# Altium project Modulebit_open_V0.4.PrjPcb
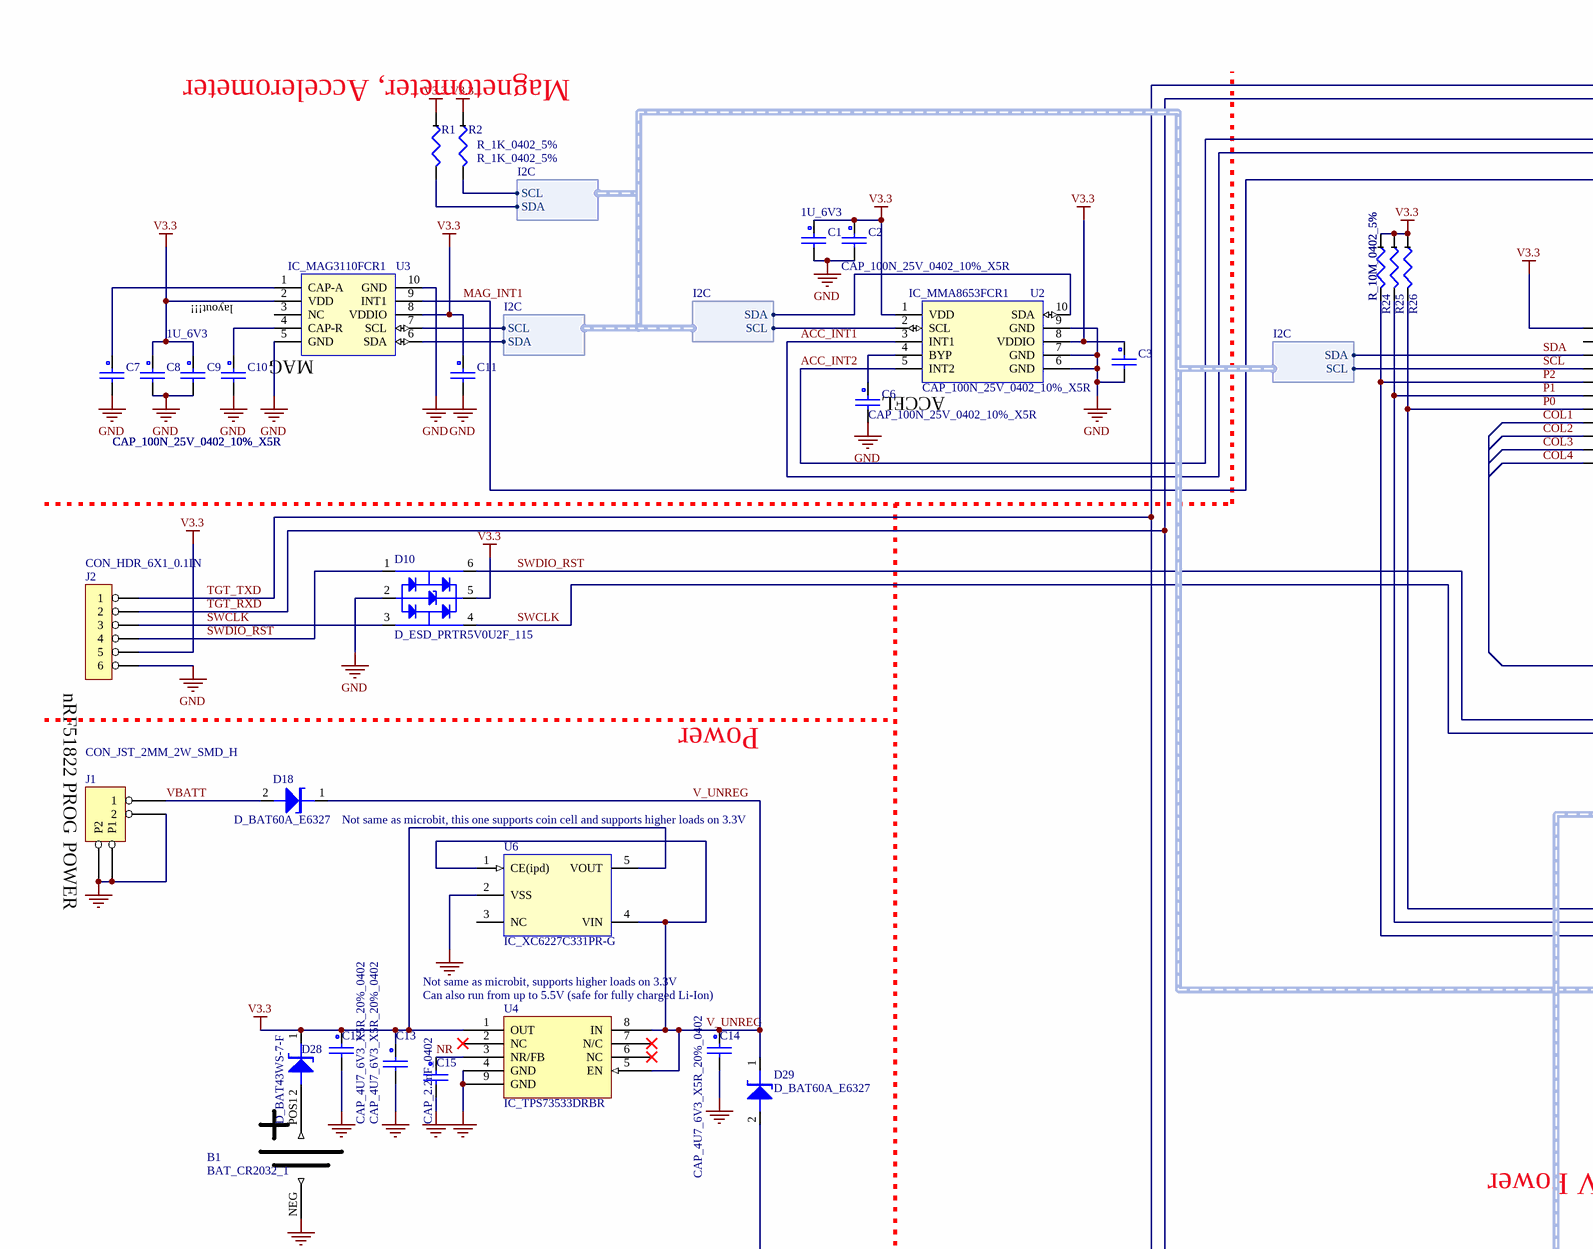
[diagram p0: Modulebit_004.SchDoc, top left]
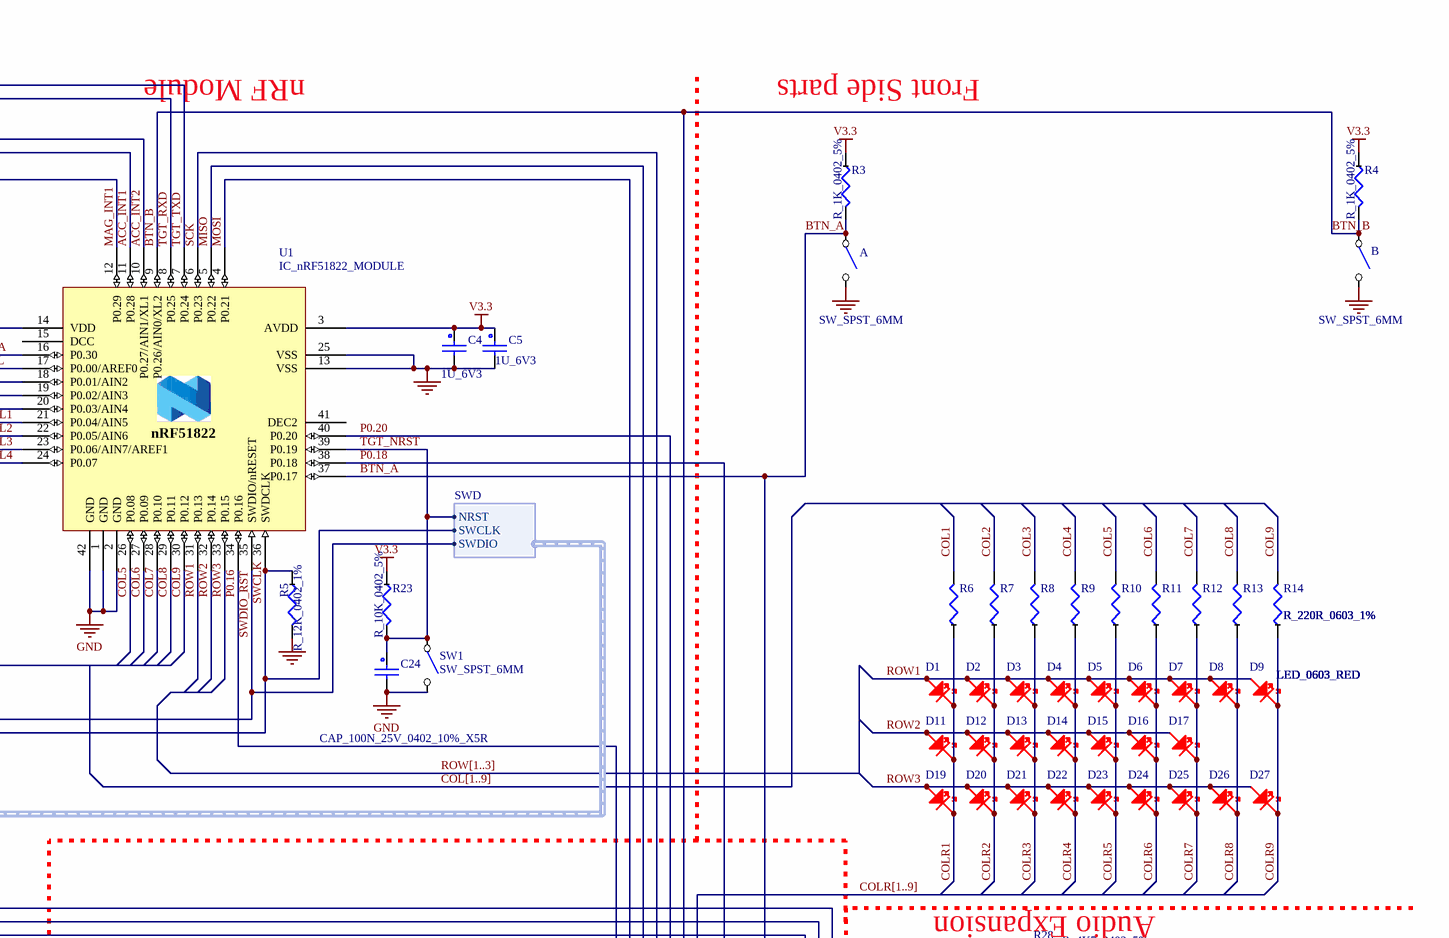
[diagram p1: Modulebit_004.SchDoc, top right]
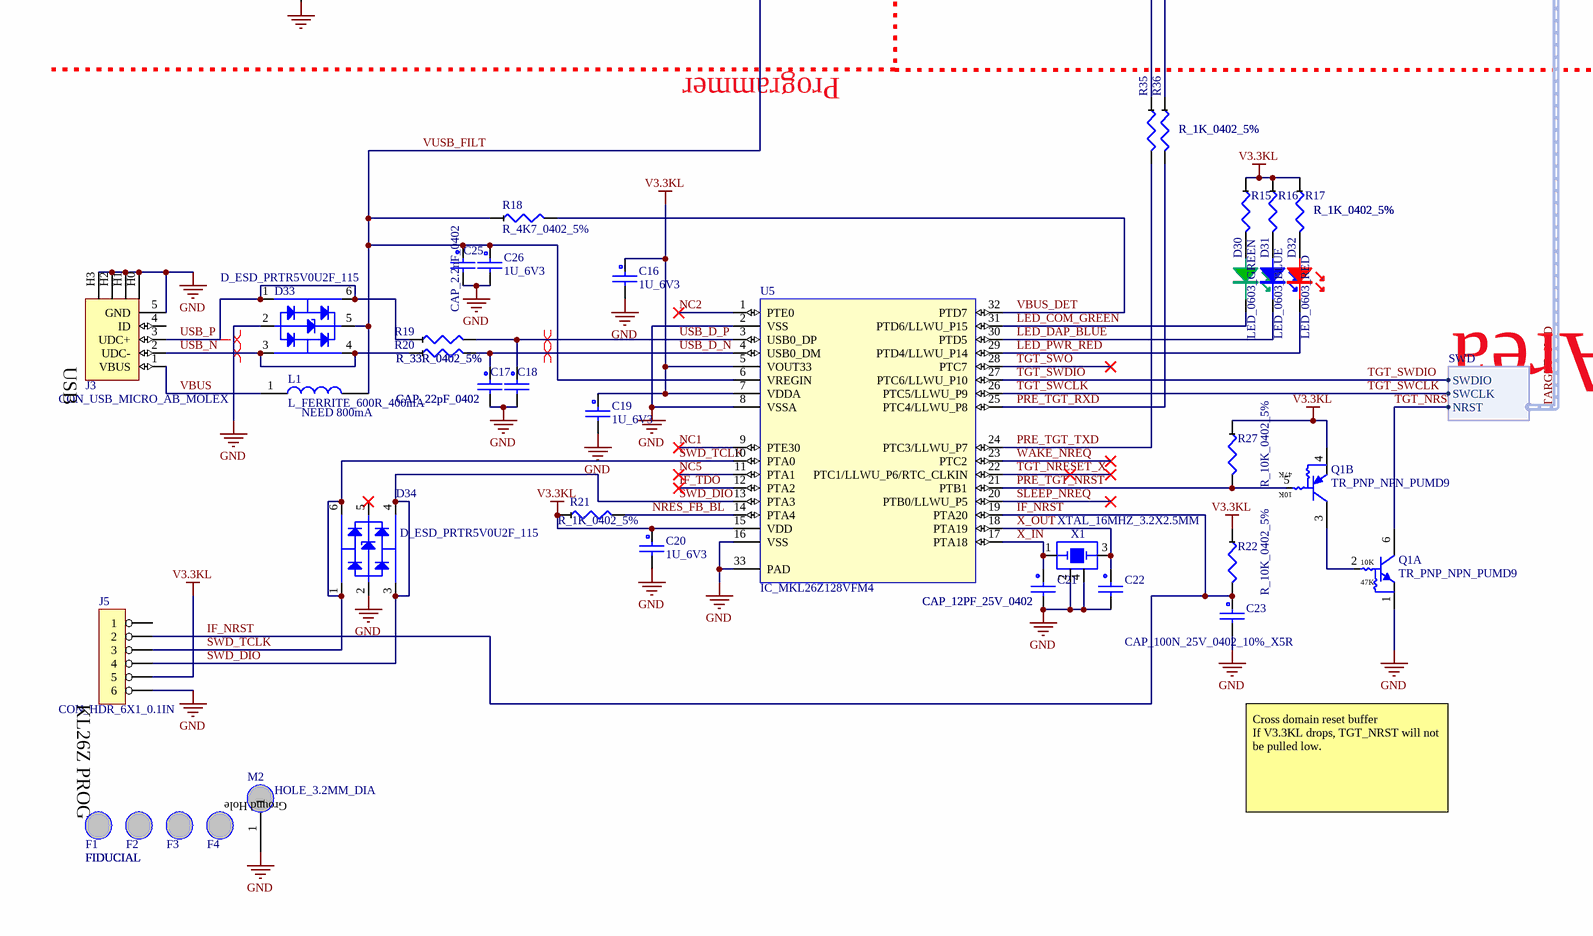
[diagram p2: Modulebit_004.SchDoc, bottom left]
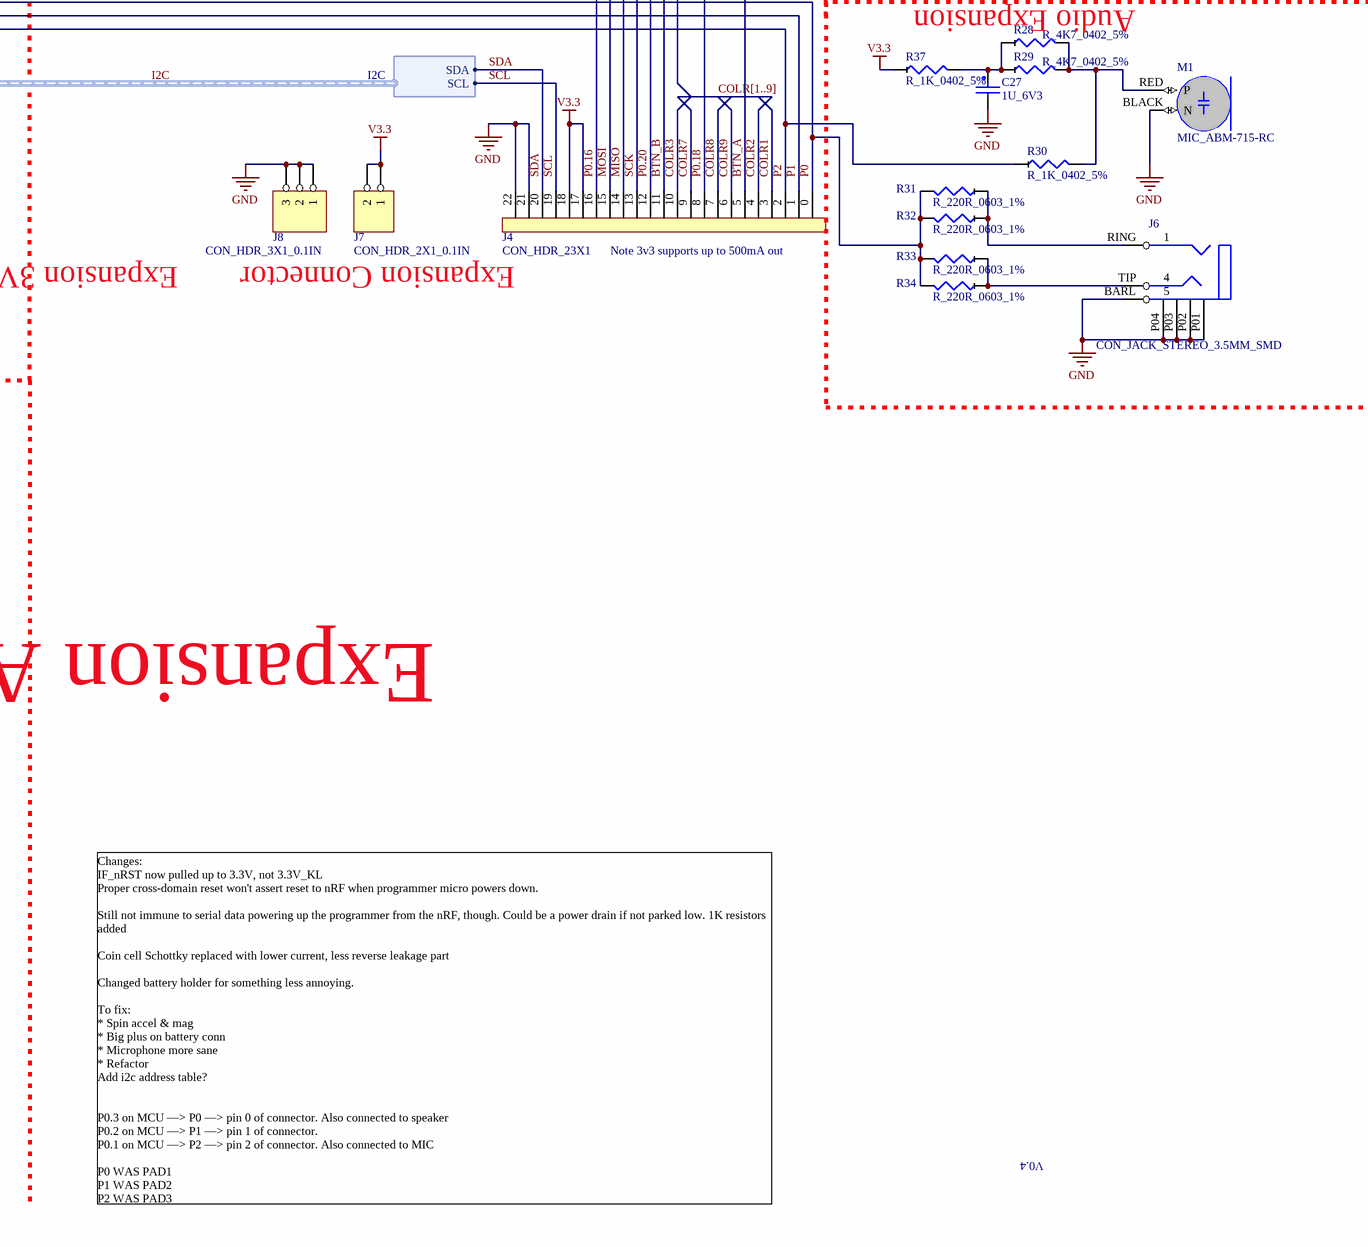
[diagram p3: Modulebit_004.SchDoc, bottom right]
1 sheet, 125 parts. Net scope: global (net labels, ports and power ports of the same name join across sheets).
Board file: ModulebitV0_4.PcbDoc

## Sheet Modulebit_004.SchDoc
size A2; Author: Steve Wiseman; Organization: Arbury.com Ltd; Address1: 2 Durnford Way; Address2: Cambridge; Address3: CB4 2DP; Address4: Unted Kingdom; DocumentNumber: 1; SheetNumber: 1; SheetTotal: 1

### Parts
A  SW_SPST_6MM  [SW_FSM4JSMA]
B  SW_SPST_6MM  [SW_FSM4JSMA]
B1  BAT_CR2032_1  [BAT_CR2032_CH7410-2032LF]
C1  1U_6V3  [C_0402]
C2  CAP_100N_25V_0402_10%_X5R  [C_0402]
C3  CAP_100N_25V_0402_10%_X5R  [C_0402]
C4  1U_6V3  [C_0402]
C5  1U_6V3  [C_0402]
C6  CAP_100N_25V_0402_10%_X5R  [C_0402]
C7  CAP_100N_25V_0402_10%_X5R  [C_0402]
C8  1U_6V3  [C_0402]
C9  CAP_100N_25V_0402_10%_X5R  [C_0402]
C10  CAP_100N_25V_0402_10%_X5R  [C_0402]
C11  CAP_100N_25V_0402_10%_X5R  [C_0402]
C12  CAP_4U7_6V3_X5R_20%_0402  [c_0402]
C13  CAP_4U7_6V3_X5R_20%_0402  [c_0402]
C14  CAP_4U7_6V3_X5R_20%_0402  [c_0402]
C15  CAP_2.2nF_0402  [C_0402]
C16  1U_6V3  [C_0402]
C17  CAP_22pF_0402  [c_0402]
C18  CAP_22pF_0402  [c_0402]
C19  1U_6V3  [C_0402]
C20  1U_6V3  [C_0402]
C21  CAP_12PF_25V_0402  [C_0402]
C22  CAP_12PF_25V_0402  [C_0402]
C23  CAP_100N_25V_0402_10%_X5R  [C_0402]
C24  CAP_100N_25V_0402_10%_X5R  [C_0402]
C25  CAP_2.2nF_0402  [C_0402]
C26  1U_6V3  [C_0402]
C27  1U_6V3  [C_0402]
D1  LED_0603_RED  [LED_0603_RED]
D2  LED_0603_RED  [LED_0603_RED]
D3  LED_0603_RED  [LED_0603_RED]
D4  LED_0603_RED  [LED_0603_RED]
D5  LED_0603_RED  [LED_0603_RED]
D6  LED_0603_RED  [LED_0603_RED]
D7  LED_0603_RED  [LED_0603_RED]
D8  LED_0603_RED  [LED_0603_RED]
D9  LED_0603_RED  [LED_0603_RED]
D10  D_ESD_PRTR5V0U2F_115  [SOT886]
D11  LED_0603_RED  [LED_0603_RED]
D12  LED_0603_RED  [LED_0603_RED]
D13  LED_0603_RED  [LED_0603_RED]
D14  LED_0603_RED  [LED_0603_RED]
D15  LED_0603_RED  [LED_0603_RED]
D16  LED_0603_RED  [LED_0603_RED]
D17  LED_0603_RED  [LED_0603_RED]
D18  D_BAT60A_E6327  [SOD323]
D19  LED_0603_RED  [LED_0603_RED]
D20  LED_0603_RED  [LED_0603_RED]
D21  LED_0603_RED  [LED_0603_RED]
D22  LED_0603_RED  [LED_0603_RED]
D23  LED_0603_RED  [LED_0603_RED]
D24  LED_0603_RED  [LED_0603_RED]
D25  LED_0603_RED  [LED_0603_RED]
D26  LED_0603_RED  [LED_0603_RED]
D27  LED_0603_RED  [LED_0603_RED]
D28  D_BAT43WS-7-F  [SOD323]
D29  D_BAT60A_E6327  [SOD323]
D30  LED_0603_GREEN  [LED_0603_GREEN]
D31  LED_0603_BLUE  [LED_0603_BLUE]
D32  LED_0603_RED  [LED_0603_RED]
D33  D_ESD_PRTR5V0U2F_115  [SOT886]
D34  D_ESD_PRTR5V0U2F_115  [SOT886]
F1  FIDUCIAL  [FIDUCIAL_OV]
F2  FIDUCIAL  [FIDUCIAL_OV]
F3  FIDUCIAL  [FIDUCIAL_OV]
F4  FIDUCIAL  [FIDUCIAL_OV]
J1  CON_JST_2MM_2W_SMD_H  [CON_JST_S2B-PH-SM4-TB]
J2  CON_HDR_6X1_0.1IN  [CON_HDR_6X1]
J3  CON_USB_MICRO_AB_MOLEX  [CON_USB_MICRO_AB_MOLEX]
J4  CON_HDR_23X1  [CON_HDR_23X1]
J5  CON_HDR_6X1_0.1IN  [CON_HDR_6X1]
J6  CON_JACK_STEREO_3.5MM_SMD  [CON_JACK_STEREO_3.5MM_SMT]
J7  CON_HDR_2X1_0.1IN  [CON_HDR_2X1]
J8  CON_HDR_3X1_0.1IN  [CON_HDR_3X1]
L1  L_FERRITE_600R_400mA  [L_0603]
M1  MIC_ABM-715-RC  [MIC_ABM-715-RC]
M2  HOLE_3.2MM_DIA  [HOLE_3.2MM_DIA]  (no BOM)
Q1  TR_PNP_NPN_PUMD9  [SOT363_N]  (parts A,B of 2)
R1  R_1K_0402_5%  [R_0402]
R2  R_1K_0402_5%  [R_0402]
R3  R_1K_0402_5%  [R_0402]
R4  R_1K_0402_5%  [R_0402]
R5  R_12K_0402_1%  [R_0402]
R6  R_220R_0603_1%  [R_0603]
R7  R_220R_0603_1%  [R_0603]
R8  R_220R_0603_1%  [R_0603]
R9  R_220R_0603_1%  [R_0603]
R10  R_220R_0603_1%  [R_0603]
R11  R_220R_0603_1%  [R_0603]
R12  R_220R_0603_1%  [R_0603]
R13  R_220R_0603_1%  [R_0603]
R14  R_220R_0603_1%  [R_0603]
R15  R_1K_0402_5%  [R_0402]
R16  R_1K_0402_5%  [R_0402]
R17  R_1K_0402_5%  [R_0402]
R18  R_4K7_0402_5%  [R_0402]
R19  R_33R_0402_5%  [R_0402]
R20  R_33R_0402_5%  [R_0402]
R21  R_1K_0402_5%  [R_0402]
R22  R_10K_0402_5%  [R_0402]
R23  R_10K_0402_5%  [R_0402]
R24  R_10M_0402_5%  [R_0402]
R25  R_10M_0402_5%  [R_0402]
R26  R_10M_0402_5%  [R_0402]
R27  R_10K_0402_5%  [R_0402]
R28  R_4K7_0402_5%  [R_0402]
R29  R_4K7_0402_5%  [R_0402]
R30  R_1K_0402_5%  [R_0402]
R31  R_220R_0603_1%  [R_0603]
R32  R_220R_0603_1%  [R_0603]
R33  R_220R_0603_1%  [R_0603]
R34  R_220R_0603_1%  [R_0603]
R35  R_1K_0402_5%  [R_0402]
R36  R_1K_0402_5%  [R_0402]
R37  R_1K_0402_5%  [R_0402]
SW1  SW_SPST_6MM  [SW_FSM4JSMA]
U1  IC_nRF51822_MODULE  [IC_nRF51822_MODULE_PASTE]
U2  IC_MMA8653FCR1  [IC_QFN40P200X200X85-10M]
U3  IC_MAG3110FCR1  [IC_QFN40P200X200X85-10M]
U4  IC_TPS73533DRBR  [IC_QFN65P300X300X100-8M-TI]
U5  IC_MKL26Z128VFM4  [IC_QFN50P500X500X100-32N]
U6  IC_XC6227C331PR-G  [SOT895]
X1  XTAL_16MHZ_3.2X2.5MM  [XTAL_3.2X2.5MM]

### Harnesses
SWD: SWDIO, SWCLK, NRST
I2C: SCL, SDA

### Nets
GND: A.2 B.2 B1.NEG C1.2 C2.2 C3.2 C4.2 C5.2 C6.2 C7.2 C8.2 C9.2 C10.2 C11.2 C12.2 C13.2 C14.2 C15.2 C16.2 C17.2 C18.2 C19.2 C20.2 C21.2 C22.2 C23.2 C24.2 C25.2 C26.2 C27.2 D10.2 D33.2 D34.2 J1.2 J1.P1 J1.P2 J2.6 J3.5(GND) J3.H0 J3.H1 J3.H2 J3.H3 J4.21 J4.22 J5.6 J6.BARL J6.P01 J6.P02 J6.P03 J6.P04 J8.1 J8.2 J8.3 M1.BLACK(N) M2.1 Q1.1(E) R5.2 SW1.2 U1.1(GND) U1.2(GND) U1.13(VSS) U1.25(VSS) U1.42(GND) U2.6(GND) U2.7(GND) U2.9(GND) U3.5(GND) U3.10(GND) U4.4(GND) U4.9(GND) U5.2(VSS) U5.8(VSSA) U5.16(VSS) U5.33(PAD) U6.2(VSS) X1.2(G2) X1.4(G4)
V3.3: C1.1 C2.1 C3.1 C4.1 C5.1 C8.1 C9.1 C11.1 C12.1 C13.1 D10.5 D28.1(K) J2.5 J4.17 J4.18 J7.1 J7.2 R1.1 R2.1 R3.1 R4.1 R23.1 R24.1 R25.1 R26.1 R37.1 U1.3(AVDD) U1.14(VDD) U2.1(VDD) U2.8(VDDIO) U3.2(VDD) U3.8(VDDIO) U4.1(OUT) U6.5(VOUT)
V3.3KL: C16.1 C19.1 C20.1 J5.5 Q1.4(E) R15.1 R16.1 R17.1 R21.1 R22.1 R27.1 U5.5(VOUT33) U5.7(VDDA) U5.15(VDD)
ACC_INT1: U1.11(P0.28) U2.3(INT1)
ACC_INT2: U1.10(P0.27/AIN1/XL1) U2.5(INT2)
BTN_A: A.1 J4.5 R3.2 U1.37(P0.17)
BTN_B: B.1 J4.11 R4.2 U1.9(P0.26/AIN0/XL2)
COL1: R6.2 U1.21(P0.04/AIN5)
COL2: R7.2 U1.22(P0.05/AIN6)
COL3: R8.2 U1.23(P0.06/AIN7/AREF1)
COL4: R9.2 U1.24(P0.07)
COL5: R10.2 U1.26(P0.08)
COL6: R11.2 U1.27(P0.09)
COL7: R12.2 U1.28(P0.10)
COL8: R13.2 U1.29(P0.11)
COL9: R14.2 U1.30(P0.12)
COLR1: D1.K D11.K D19.K J4.3 R6.1
COLR2: D2.K D12.K D20.K J4.4 R7.1
COLR3: D3.K D13.K D21.K J4.10 R8.1
COLR4: D4.K D14.K D22.K R9.1
COLR5: D5.K D15.K D23.K R10.1
COLR6: D6.K D16.K D24.K R11.1
COLR7: D7.K D17.K D25.K J4.9 R12.1
COLR8: D8.K D26.K J4.7 R13.1
COLR9: D9.K D27.K J4.6 R14.1
IF_NRST: C23.1 J5.2 R22.2 U5.19(PTA20)
IF_TDO: U5.12(PTA2)
LED_COM_GREEN: D30.K U5.31(PTD6/LLWU_P15)
LED_DAP_BLUE: D31.K U5.30(PTD5)
LED_PWR_RED: D32.K U5.29(PTD4/LLWU_P14)
MAG_INT1: U1.12(P0.29) U3.9(INT1)
MISO: J4.14 U1.5(P0.22)
MOSI: J4.15 U1.4(P0.21)
NC1: U5.9(PTE30)
NC2: U5.1(PTE0)
NC5: U5.11(PTA1)
NR: C15.1 U4.3(NR/FB)
NRES_FB_BL: R21.2 U5.14(PTA4)
P0: J4.0 R26.2 R31.2 R32.2 R33.2 R34.2 U1.20(P0.03/AIN4)
P0.16: J4.16 U1.34(P0.16)
P0.18: J4.8 U1.38(P0.18)
P0.20: J4.12 U1.40(P0.20)
P1: J4.1 R25.2 U1.19(P0.02/AIN3)
P2: J4.2 R24.2 R30.1 U1.18(P0.01/AIN2)
PRE_TGT_NRST: Q1.5(B) R27.2 U5.21(PTB1)
PRE_TGT_RXD: R36.2 U5.25(PTC4/LLWU_P8)
PRE_TGT_TXD: R35.2 U5.24(PTC3/LLWU_P7)
ROW1: D1.A D2.A D3.A D4.A D5.A D6.A D7.A D8.A D9.A U1.31(P0.13)
ROW2: D11.A D12.A D13.A D14.A D15.A D16.A D17.A U1.32(P0.14)
ROW3: D19.A D20.A D21.A D22.A D23.A D24.A D25.A D26.A D27.A U1.33(P0.15)
SCK: J4.13 U1.6(P0.23)
SCL: J4.19 R2.2 U1.17(P0.00/AREF0) U2.2(SCL) U3.7(SCL) ; harness I2C.SCL  [project net I2C.SCL]
SDA: J4.20 R1.2 U1.16(P0.30) U2.10(SDA) U3.6(SDA) ; harness I2C.SDA  [project net I2C.SDA]
SLEEP_NREQ: U5.20(PTB0/LLWU_P5)
SWCLK: D10.3 D10.4 J2.3 R5.1 U1.36(SWDCLK) U5.26(PTC5/LLWU_P9) ; harness SWD.SWCLK  [also labelled TGT_SWCLK]
SWD_DIO: D34.3 D34.4 J5.4 U5.13(PTA3)
SWD_TCLK: D34.1 D34.6 J5.3 U5.10(PTA0)
SWDIO_RST: D10.1 D10.6 J2.4 U1.35(SWDIO/nRESET) U5.27(PTC6/LLWU_P10) ; harness SWD.SWDIO  [also labelled TGT_SWDIO]
TGT_NRESET_X: U5.22(PTC1/LLWU_P6/RTC_CLKIN)
TGT_NRST: C24.1 Q1.6(C) R23.2 SW1.1 U1.39(P0.19) ; harness SWD.NRST  [project net TARGET_SWD.NRST]
TGT_RXD: J2.2 R36.1 U1.8(P0.25)
TGT_SWO: U5.28(PTC7)
TGT_TXD: J2.1 R35.1 U1.7(P0.24)
USB_D_N: C17.1 R20.2 U5.4(USB0_DM)
USB_D_P: C18.1 R19.2 U5.3(USB0_DP)
USB_N: D33.3 D33.4 J3.2(UDC-) R20.1
USB_P: D33.1 D33.6 J3.3(UDC+) R19.1
V_UNREG: C14.1 D18.1(K) D29.1(K) U4.5(EN) U4.8(IN) U6.1(CE(ipd)) U6.4(VIN)
VBATT: D18.2(A) J1.1
VBUS: J3.1(VBUS) L1.1
VBUS_DET: R18.2 U5.32(PTD7)
VUSB_FILT: C25.1 C26.1 D29.2(A) D33.5 L1.2 R18.1 U5.6(VREGIN)
WAKE_NREQ: U5.23(PTC2)
X_IN: C21.1 U5.17(PTA18) X1.1(X1)
X_OUT: C22.1 U5.18(PTA19) X1.3(X3)
NetB1_POS1: B1.POS1 D28.2(A)
NetC6_1: C6.1 U2.4(BYP)
NetC7_1: C7.1 U3.1(CAP-A)
NetC10_1: C10.1 U3.4(CAP-R)
NetC27_1: C27.1 R28.1 R29.1 R37.2
NetD30_A: D30.A R15.2
NetD31_A: D31.A R16.2
NetD32_A: D32.A R17.2
NetJ6_RING: J6.RING R31.1 R32.1
NetJ6_TIP: J6.TIP R33.1 R34.1
NetM1_RED: M1.RED(P) R28.2 R29.2 R30.2
NetQ1_2: Q1.2(B) Q1.3(C)

Not connected (* = marked no-connect by the designer): D34 5*; F1 1; F2 1; F3 1; F4 1; J3 4(ID); J5 1; U1 15(DCC) 41(DEC2); U3 3(NC); U4 2(NC)* 6(NC)* 7(N/C)*; U6 3(NC)

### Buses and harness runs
bus COL[1..9]
bus COLR[1..9]
bus ROW[1..3]

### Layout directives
differential pair: USB_D_N, USB_D_P, USB_N, USB_P

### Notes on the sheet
- Magnetometer, Accelerometer
- nRF Module
- Front Side parts
- (near U3) layout!!!
- (near U3) MAG
- (near U2) ACCEL
- (near J2) nRF51822 PROG
- Power
- Not same as microbit, this one supports coin cell and supports higher loads on 3.3V
- (near J1) POWER
- Audio Expansion
- Not same as microbit, supports higher loads on 3.3V
- Can also run from up to 5.5V (safe for fully charged Li-Ion)
- Expansion 3V Power
- (near J4) Expansion Connector
- (near J4) Note 3v3 supports up to 500mA out
- Programmer
- Expansion Area
- (near J3) USB
- (near L1) NEED 800mA
- (near J5) KL26Z PROG
- (near M2) Ground Hole
- Cross domain reset buffer
  If V3.3KL drops, TGT_NRST will not be pulled low.
- Changes:
  IF_nRST now pulled up to 3.3V, not 3.3V_KL
  Proper cross-domain reset won't assert reset to nRF when programmer micro powers down.
  Still not immune to serial data powering up the programmer from the nRF, though. Could be a power drain if not parked low. 1K resistors added
  Coin cell Schottky replaced with lower current, less reverse leakage part
  Changed battery holder for something less annoying.
  To fix:
  * Spin accel & mag
  * Big plus on battery conn
  * Microphone more sane
  * Refactor
  Add i2c address table?
  P0.3 on MCU —> P0 —> pin 0 of connector. Also connected to speaker
  P0.2 on MCU —> P1 —> pin 1 of connector.
  P0.1 on MCU —> P2 —> pin 2 of connector. Also connected to MIC
  P0 WAS PAD1
  P1 WAS PAD2
  P2 WAS PAD3
- V0.4

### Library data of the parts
A B SW1 = SW_SPST_6MM: SPST SWITCH 6MM; PART: FSM4JSMA; MANUFACTURER: TE CONNECTIVITY / ALCOSWITCH
B1 = BAT_CR2032_1: CR2032 battery in holder; PART: CH7410-2032LF; MANUFACTURER: Takachi Electric Industrial; RS: 239-592
C1 C4 C5 C8 C16 C19 C20 C26 C27 = CAP_1u_6V3_0402_10%_X6S: MANUFACTURER: YAGEO; PART: CC0402KRX7R7BB104
C2 C3 C6 C7 C9-C11 C23 C24 = CAP_100N_25V_0402_10%_X5R: PART: TMK105BJ104KV-F; MANUFACTURER: TAIYO YUDEN
C12-C14 = CAP_4U7_6V3_X5R_20%_0402: PART: C1005X5R0J475M; MANUFACTURER: TDK
C15 C25 = CAP_2.2nF_0402: PART: GRM155R71H222KA01D; MANUFACTURER: MURATA
C17 C18 = CAP_22pF_0402: CAP 0402 C0G 50V 22PF; PART: 04025A220JAT2A; MANUFACTURER: AVX
D1-D9 D11-D17 D19-D27 = LED_0603_RED: LED RED 0603; PART: KP-1608SURC; MANUFACTURER: KINGBRIGHT
D10 D33 D34 = D_ESD_PRTR5V0U2F_115: Ultra low capacitance double rail-to-rail ESD protection; MANUFACTURER: NXP
D18 D29 = D_BAT60A_E6327: 3A Schottky diode with extreme low V  F drop (typ. 0.12V at IF = 10mA); MANUFACTURER: INFINEON; PART: BAT 60A E6327
D28 = D_BAT43WS-7-F: Schottky 200mA 30V 0.5uA@25Vr; MANUFACTURER: Diodes Incorporated; RS: 751-3364P
D30 = LED_0603_GREEN: MANUFACTURER: KINGBRIGHT; PART: KP-3216CGCK
D31 = LED_0603_BLUE: MANUFACTURER: MULTICOMP
D32 = LED_0603_RED: LED RED 0603; MANUFACTURER: KINGBRIGHT; PART: KP-1608SURC
F1-F4 = FIDUCIAL: FIDUCIAL - NO CONNECT; MANUFACTURER: PCB FEATURE; Text Field1: NOT A PART
J1 = CON_JST_2MM_2W_SMD_H: 2 PIN 2MM SMT JST  CONNECTOR; PART: S2B-PH-SM4-TB(LF)(SN)
J2 = CON_HDR_6X1_0.1IN: 6 PIN HEADER; MANUFACTURER: TE; PART: 826629-6
J3 = CON_USB_MICRO_AB_MOLEX: USB Micro-AB socket Molex 47589-0001; RS: 702-5488
J4 = CON_HDR_23X1: 0.1in HEADER STRIP 23X1; PART: TSW-123-07-T-S; MANUFACTURER: SAMTEC
J5 = CON_HDR_6X1_0.1IN: 6 PIN HEADER; PART: 826629-6; MANUFACTURER: TE
J6 = CON_JACK_STEREO_3.5MM_SMD: 3.5 MM STEREO SMT JACK SOCKET SMD; PART: 1503 03; MANUFACTURER: LUMBERG
J7 = CON_HDR_2X1_0.1IN: 2 PIN HEADER; MANUFACTURER: TE CONNECTIVITY / AMP; PART: 825433-2
J8 = CON_HDR_3X1_0.1IN: 3 PIN HEADER; MANUFACTURER: MOLEX
L1 = L_FERRITE_600R_400mA: FERRITE 600R 400mA 0.35R  IN 0603; MANUFACTURER: FAIR-RITE; PART: 2506036017Y0
M1 = MIC_ABM-715-RC: PRO SIGNAL  ABM-715-RC  ELECTRET MICROPHONE OMNI LEADS
M2 = HOLE_3.2MM_DIA: HOLE, 3.2MM DIA FINISHED
Q1 = TR_PNP_NPN_PUMD9: NXP - PUMD9 - TRANSISTOR, DIGITAL, NPN+PNP SOT-363
R6-R14 R31-R34 = R_220R_0603_1%: Text Field1: 9330801; Text Field2: vnr160; Text Field3: Yes; Text Field4: 502-468-00-00-RES*-BP
R18 R28 R29 = R_4K7_0402_5%: Text Field1: 3898635
R19 R20 = R_33R_0402_5%: Text Field1: 3898507
R24-R26 = R_10M_0402_5%: PART: RC0603FR-0710ML; MANUFACTURER: YAGEO
U1 = IC_nRF51822_MODULE: RF System on a Chip - SoC 2.4GHz BT low Energy 256KB Flash 16KB Ram; MANUFACTURER: RAYTAC; PART: MDBT40-256V3
U2 = IC_MMA8653FCR1: 3-Axis 10-bit Digital  Accelerometer; MANUFACTURER: FREESCALE; RS: 801-6882
U3 = IC_MAG3110FCR1: Three-Axis Digital  Magnetometer; MANUFACTURER: FREESCALE; RS: 750-0835
U4 = IC_TPS73533DRBR: TPS735 500-mA 3V3, Low Quiescent Current, Ultra-Low Noise, High PSRR,  Low-Dropout Linear Regulator; MANUFACTURER: TI
U5 = IC_MKL26Z128VFM4: 32bit ARM Cortex M0+ Microcontroller 48MHz 128 kB Flash 32-Pin QFN; MANUFACTURER: NXP; RS: 818-1255
U6 = IC_XC6227C331PR-G: Linear Voltage Regulator IC Positive Fixed 1 Output 3.3V 700mA SOT-89-5; MANUFACTURER: TOREX
X1 = XTAL_16MHZ_3.2X2.5MM: CRYSTAL 16MHZ 20PF_3.2X2.5MM; MANUFACTURER: CTS-Frequency Controls; PART: 403C11E16M00000

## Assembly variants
FIRSTBUILD: not fitted C15 J2 J4 J5 J7 J8 U6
